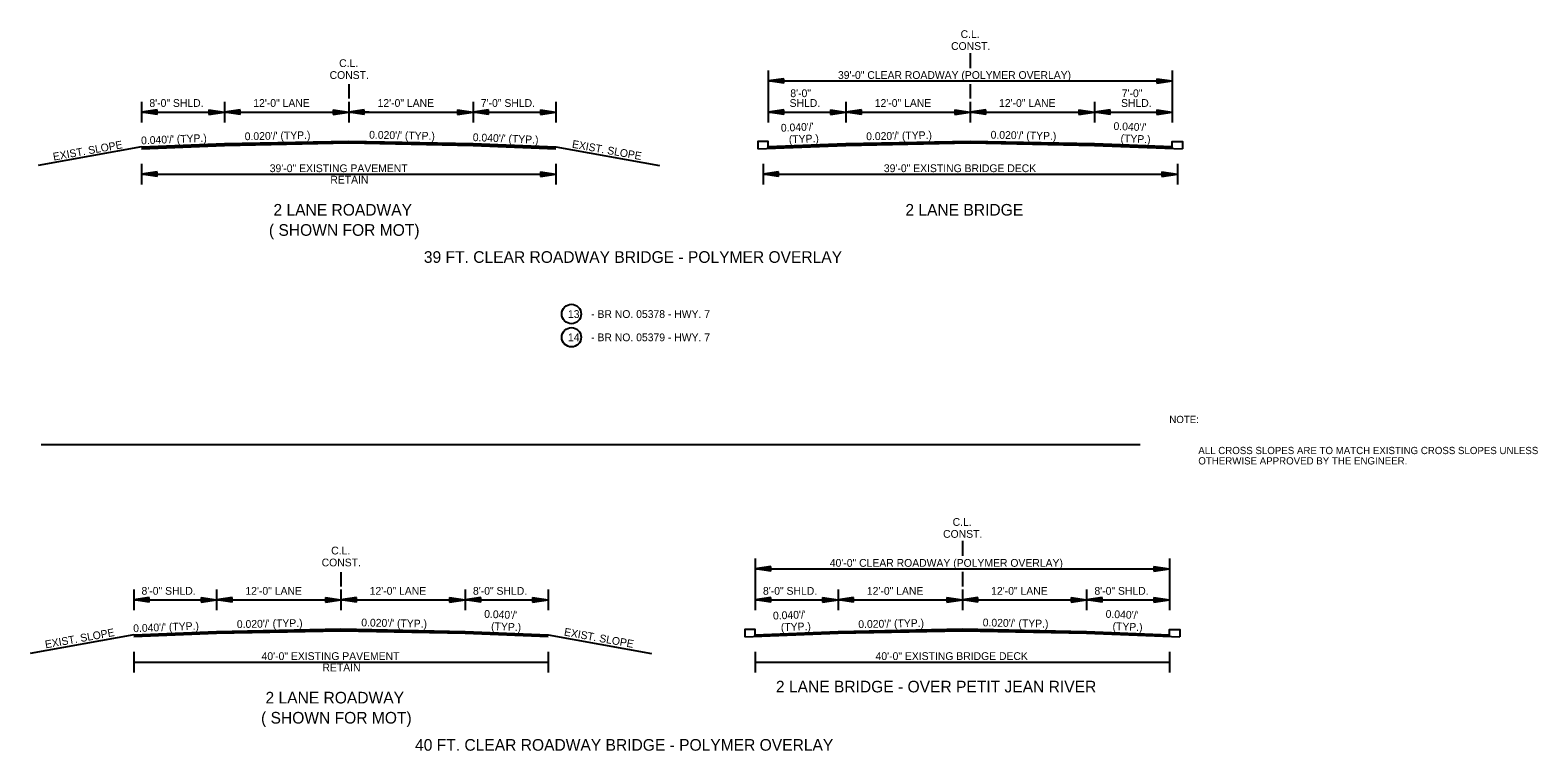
# Model space of a CAD drawing. Extents: x 550980 to 1930787, y -1972975 to 596640.
# Drawn here: x 550998 to 552454, y -1951534 to -1950838 of the extents above; entities that cross this region are included whole.
import ezdxf

# ---------------------------------------------------------------- set-up
doc = ezdxf.new("R2010")
doc.units = 0
for name, color, linetype in [('R_Border', 7, 'Continuous'), ('R_Border Notes', 7, 'Continuous'), ('R_Draft', 7, 'Continuous')]:
    doc.layers.add(name, color=color, linetype=linetype)

# ---------------------------------------------------------------- blocks, each defined once
blk = doc.blocks.new('ARROW')
at = {"layer": 'R_Draft'}
for p, q in [((-2, 0.3), (0, 0)), ((-2, 0.3), (-2, -0.3)), ((-2, 0.25), (-0.334, 0)), ((-2, 0.199), (-0.678, 0)), ((-2, 0.149), (-1.011, 0)), ((-2, 0.097), (-1.35, 0)), ((-2, 0.047), (-1.684, 0)), ((-2, -0.3), (0, 0)), ((-2, -0.098), (-1.35, 0)), ((-2, -0.199), (-0.678, 0)), ((-2, -0.25), (-0.334, 0)), ((-2, -0.149), (-1.011, 0)), ((-2, -0.047), (-1.684, 0))]:
    blk.add_line(p, q, dxfattribs=at)
blk = doc.blocks.new('BPPOLY')
at = {"layer": 'R_Border'}
blk.add_circle((0, 0), 9.34, dxfattribs=at)

msp = doc.modelspace()

# ---------------------------------------------------------------- linework, layer by layer
at = {"layer": 'R_Border'}
for p, q in [((551906.1, -1950859.9), (551906.1, -1950874.4)), ((551711.1, -1950876.9), (551711.1, -1950926.9)), ((552101.1, -1950876.9), (552101.1, -1950926.9)), ((551306.1, -1950889.9), (551306.1, -1950903.9)), ((551711.1, -1950886.9), (552101.1, -1950886.9)), ((551906.1, -1950889.9), (551906.1, -1950903.9)), ((551106.1, -1950906.9), (551106.1, -1950926.9)), ((551186.1, -1950906.9), (551186.1, -1950926.9)), ((551306.1, -1950906.9), (551306.1, -1950926.9)), ((551426.1, -1950906.9), (551426.1, -1950926.9)), ((551506.1, -1950906.9), (551506.1, -1950926.9)), ((551786.1, -1950906.9), (551786.1, -1950926.9)), ((551906.1, -1950906.9), (551906.1, -1950926.9)), ((552026.1, -1950906.9), (552026.1, -1950926.9)), ((551106.1, -1950916.9), (551506.1, -1950916.9)), ((551305.9, -1950916.6), (551325.9, -1950916.6)), ((551711.1, -1950916.9), (552101.1, -1950916.9)), ((551106.1, -1950950.5), (551006.1, -1950968.5)), ((551506.1, -1950950.5), (551606.1, -1950968.5)), ((551106.1, -1950966.9), (551106.1, -1950986.9)), ((551506.1, -1950966.9), (551506.1, -1950986.9)), ((551706.1, -1950966.9), (551706.1, -1950986.9)), ((552106.1, -1950966.9), (552106.1, -1950986.9)), ((551106.1, -1950976.9), (551506.1, -1950976.9)), ((551706.1, -1950976.9), (552106.1, -1950976.9)), ((551009, -1951237.9), (552070.2, -1951237.9)), ((551898.5, -1951331), (551898.5, -1951345.5)), ((551698.5, -1951348), (551698.5, -1951398)), ((551698.5, -1951358), (552098.5, -1951358)), ((551898.5, -1951361), (551898.5, -1951375)), ((552098.5, -1951348), (552098.5, -1951398)), ((551298.5, -1951361.3), (551298.5, -1951375)), ((551098.5, -1951378), (551098.5, -1951398)), ((551098.5, -1951388), (551498.5, -1951388)), ((551178.5, -1951378), (551178.5, -1951398)), ((551298.5, -1951378), (551298.5, -1951398)), ((551418.5, -1951378), (551418.5, -1951398)), ((551498.5, -1951378), (551498.5, -1951398)), ((551698.5, -1951388), (552098.5, -1951388)), ((551778.5, -1951378), (551778.5, -1951398)), ((551898.5, -1951378), (551898.5, -1951398)), ((552018.5, -1951378), (552018.5, -1951398)), ((551098.5, -1951421.6), (550998.5, -1951439.6)), ((551498.5, -1951421.6), (551598.5, -1951439.6)), ((551098.5, -1951438), (551098.5, -1951458)), ((551098.5, -1951448), (551498.5, -1951448)), ((551498.5, -1951438), (551498.5, -1951458)), ((551698.5, -1951438), (551698.5, -1951458)), ((551698.5, -1951448), (552098.5, -1951448)), ((552098.5, -1951438), (552098.5, -1951458))]:
    msp.add_line(p, q, dxfattribs=at)
for points in [[(551106.1, -1950950.5), (551186.1, -1950947.3), (551306.1, -1950944.9), (551426.1, -1950947.3), (551506.1, -1950950.5)], [(551106.1, -1950950.8), (551186.1, -1950947.6), (551306.1, -1950945.2), (551426.1, -1950947.6), (551506.1, -1950950.8)], [(551106.1, -1950951.1), (551186.1, -1950947.9), (551306.1, -1950945.5), (551426.1, -1950947.9), (551506.1, -1950951.1)], [(551106.1, -1950951.4), (551186.1, -1950948.2), (551306.1, -1950945.8), (551426.1, -1950948.2), (551506.1, -1950951.4)], [(551106.1, -1950951.7), (551186.1, -1950948.5), (551306.1, -1950946.1), (551426.1, -1950948.5), (551506.1, -1950951.7)], [(551106.1, -1950952), (551186.1, -1950948.8), (551306.1, -1950946.4), (551426.1, -1950948.8), (551506.1, -1950952)], [(551106.1, -1950952.3), (551186.1, -1950949.1), (551306.1, -1950946.7), (551426.1, -1950949.1), (551506.1, -1950952.3)], [(551711.1, -1950951.8), (551711.1, -1950945.3), (551701.1, -1950945.3), (551701.1, -1950952.5)], [(551701.1, -1950952.5), (551786.1, -1950949.1), (551906.1, -1950946.7), (552026.1, -1950949.1), (552111.1, -1950952.5)], [(551711.1, -1950950.3), (551786.1, -1950947.3), (551906.1, -1950944.9), (552026.1, -1950947.3), (552101.1, -1950950.3)], [(551711.1, -1950950.6), (551786.1, -1950947.6), (551906.1, -1950945.2), (552026.1, -1950947.6), (552101.1, -1950950.6)], [(551711.1, -1950950.9), (551786.1, -1950947.9), (551906.1, -1950945.5), (552026.1, -1950947.9), (552101.1, -1950950.9)], [(551711.1, -1950951.2), (551786.1, -1950948.2), (551906.1, -1950945.8), (552026.1, -1950948.2), (552101.1, -1950951.2)], [(551711.1, -1950951.5), (551786.1, -1950948.5), (551906.1, -1950946.1), (552026.1, -1950948.5), (552101.1, -1950951.5)], [(551711.1, -1950951.8), (551786.1, -1950948.8), (551906.1, -1950946.4), (552026.1, -1950948.8), (552101.1, -1950951.8)], [(552101.1, -1950951.8), (552101.1, -1950945.3), (552111.1, -1950945.3), (552111.1, -1950952.5)], [(551098.5, -1951421.6), (551178.5, -1951418.4), (551298.5, -1951416), (551418.5, -1951418.4), (551498.5, -1951421.6)], [(551098.5, -1951421.9), (551178.5, -1951418.7), (551298.5, -1951416.3), (551418.5, -1951418.7), (551498.5, -1951421.9)], [(551098.5, -1951422.2), (551178.5, -1951419), (551298.5, -1951416.6), (551418.5, -1951419), (551498.5, -1951422.2)], [(551098.5, -1951422.5), (551178.5, -1951419.3), (551298.5, -1951416.9), (551418.5, -1951419.3), (551498.5, -1951422.5)], [(551098.5, -1951422.8), (551178.5, -1951419.6), (551298.5, -1951417.2), (551418.5, -1951419.6), (551498.5, -1951422.8)], [(551098.5, -1951423.1), (551178.5, -1951419.9), (551298.5, -1951417.5), (551418.5, -1951419.9), (551498.5, -1951423.1)], [(551098.5, -1951423.4), (551178.5, -1951420.2), (551298.5, -1951417.8), (551418.5, -1951420.2), (551498.5, -1951423.4)], [(551698.5, -1951423.1), (551698.5, -1951416.6), (551688.5, -1951416.6), (551688.5, -1951423.8)], [(551688.5, -1951423.8), (551778.5, -1951420.2), (551898.5, -1951417.8), (552018.5, -1951420.2), (552108.5, -1951423.8)], [(551698.5, -1951421.6), (551778.5, -1951418.4), (551898.5, -1951416), (552018.5, -1951418.4), (552098.5, -1951421.6)], [(551698.5, -1951421.9), (551778.5, -1951418.7), (551898.5, -1951416.3), (552018.5, -1951418.7), (552098.5, -1951421.9)], [(551698.5, -1951422.2), (551778.5, -1951419), (551898.5, -1951416.6), (552018.5, -1951419), (552098.5, -1951422.2)], [(551698.5, -1951422.5), (551778.5, -1951419.3), (551898.5, -1951416.9), (552018.5, -1951419.3), (552098.5, -1951422.5)], [(551698.5, -1951422.8), (551778.5, -1951419.6), (551898.5, -1951417.2), (552018.5, -1951419.6), (552098.5, -1951422.8)], [(551698.5, -1951423.1), (551778.5, -1951419.9), (551898.5, -1951417.5), (552018.5, -1951419.9), (552098.5, -1951423.1)], [(552098.5, -1951423.8), (552098.5, -1951416.6), (552108.5, -1951416.6), (552108.5, -1951423.8)]]:
    msp.add_lwpolyline(points, dxfattribs=at)

# ---------------------------------------------------------------- block references
at = {"layer": 'R_Border', "xscale": 7.5, "yscale": 7.5, "rotation": 180}
for p in [(551711.1, -1950886.9), (551106.1, -1950916.9), (551186.1, -1950916.9), (551306.1, -1950916.9), (551426.1, -1950916.9), (551711.1, -1950916.9), (551786.1, -1950916.9), (551906.1, -1950916.9), (552026.1, -1950916.9), (551106.1, -1950976.9), (551706.1, -1950976.9), (551698.5, -1951358), (551098.5, -1951388), (551178.5, -1951388), (551298.5, -1951388), (551418.5, -1951388), (551698.5, -1951388), (551778.5, -1951388), (551898.5, -1951388), (552018.5, -1951388)]:
    msp.add_blockref('ARROW', p, dxfattribs=at)
at = {"layer": 'R_Border', "xscale": 7.5, "yscale": 7.5}
for p in [(552101.1, -1950886.9), (551186.1, -1950916.9), (551306.1, -1950916.9), (551426.1, -1950916.9), (551506.1, -1950916.9), (551786.1, -1950916.9), (551906.1, -1950916.9), (552026.1, -1950916.9), (552101.1, -1950916.9), (551506.1, -1950976.9), (552106.1, -1950976.9), (552098.5, -1951358), (551178.5, -1951388), (551298.5, -1951388), (551418.5, -1951388), (551498.5, -1951388), (551778.5, -1951388), (551898.5, -1951388), (552018.5, -1951388), (552098.5, -1951388)]:
    msp.add_blockref('ARROW', p, dxfattribs=at)
at = {"layer": 'R_Border'}
for p in [(551521.1, -1951111.9), (551521.1, -1951134.4)]:
    msp.add_blockref('BPPOLY', p, dxfattribs=at)

# ---------------------------------------------------------------- texts
for s, height, p in [('CONST.', 7.5, (551887.6, -1950856.9)), ('C.L.', 7.5, (551896.8, -1950845.4)), ('C.L.', 7.5, (551296.8, -1950873.4)), ('CONST.', 7.5, (551287.6, -1950884.9)), ('39\'-0" CLEAR ROADWAY (POLYMER OVERLAY)', 7.5, (551778.4, -1950884.9)), ('8\'-0" ', 7.5, (551732.4, -1950902.5)), ('7\'-0" ', 7.5, (552052.4, -1950902.5)), ('8\'-0" SHLD.', 7.5, (551113.6, -1950911.9)), ('12\'-0" LANE', 7.5, (551213.9, -1950911.9)), ('12\'-0" LANE', 7.5, (551333.9, -1950911.9)), ('7\'-0" SHLD.', 7.5, (551433.6, -1950911.9)), ('SHLD.', 7.5, (551731.7, -1950911.9)), ('12\'-0" LANE', 7.5, (551813.9, -1950911.9)), ('12\'-0" LANE', 7.5, (551933.9, -1950911.9)), ('SHLD.', 7.5, (552051.7, -1950911.9)), ('39\'-0" EXISTING PAVEMENT', 7.5, (551229.8, -1950974.9)), ('39\'-0" EXISTING BRIDGE DECK', 7.5, (551822.7, -1950974.9)), ('RETAIN', 7.5, (551288.3, -1950985.9)), ('2 LANE ROADWAY', 11.25, (551233.4, -1951016.9)), ('2 LANE BRIDGE', 11.25, (551843.5, -1951016.9)), ('( SHOWN FOR MOT)', 11.25, (551229, -1951036.4)), ('39 FT. CLEAR ROADWAY BRIDGE - POLYMER OVERLAY', 11.25, (551378.6, -1951062.5)), ('13', 7.5, (551517.7, -1951115.7)), ('- BR NO. 05378 - HWY. 7', 7.5, (551540.1, -1951115.7)), ('14', 7.5, (551517.7, -1951138.2)), ('- BR NO. 05379 - HWY. 7', 7.5, (551540.1, -1951138.2)), ('C.L.', 7.5, (551889.1, -1951316.5)), ('CONST.', 7.5, (551879.9, -1951328)), ('C.L.', 7.5, (551289.1, -1951344.1)), ('CONST.', 7.5, (551279.9, -1951355.6)), ('40\'-0" CLEAR ROADWAY (POLYMER OVERLAY)', 7.5, (551770.5, -1951356)), ('8\'-0" SHLD.', 7.5, (551106, -1951383)), ('12\'-0" LANE', 7.5, (551206.3, -1951383)), ('12\'-0" LANE', 7.5, (551326.3, -1951383)), ('8\'-0" SHLD.', 7.5, (551426, -1951383)), ('8\'-0" SHLD.', 7.5, (551706, -1951383)), ('12\'-0" LANE', 7.5, (551806.3, -1951383)), ('12\'-0" LANE', 7.5, (551926.3, -1951383)), ('8\'-0" SHLD.', 7.5, (552026, -1951383)), ('40\'-0" EXISTING PAVEMENT', 7.5, (551221.9, -1951446)), ('40\'-0" EXISTING BRIDGE DECK', 7.5, (551814.7, -1951446)), ('RETAIN', 7.5, (551280.7, -1951457)), ('2 LANE ROADWAY', 11.25, (551225.7, -1951488)), ('2 LANE BRIDGE - OVER PETIT JEAN RIVER', 11.25, (551718.5, -1951477.3)), ('( SHOWN FOR MOT)', 11.25, (551221.4, -1951507.4)), ('40 FT. CLEAR ROADWAY BRIDGE - POLYMER OVERLAY', 11.25, (551370.1, -1951533.6))]:
    msp.add_text(s, height=height, dxfattribs=at).set_placement(p)
for s, rotation, p in [("0.040'/' (TYP.)", 2.2916, (551105.7, -1950948.1)), ("0.020'/' (TYP.)", 1.1458, (551205.7, -1950944.1)), ("0.020'/' (TYP.)", 358.8542, (551325.7, -1950942.5)), ("0.040'/' (TYP.)", 357.7084, (551425.7, -1950944.9)), ("0.040'/'", 2.2916, (551723.4, -1950935.9)), ('(TYP.)', 2.2916, (551731.1, -1950947.1)), ("0.020'/' (TYP.)", 1.1458, (551805.7, -1950944.1)), ("0.020'/' (TYP.)", 358.8542, (551925.7, -1950942.5)), ("0.040'/'", 357.7084, (552044.3, -1950934.1)), ('(TYP.)', 357.7084, (552051.1, -1950945.9)), ('EXIST. SLOPE', 10.204, (551021.2, -1950963.8)), ('EXIST. SLOPE', 349.796, (551521.2, -1950951.2)), ("0.040'/'", 357.7084, (551436.7, -1951405.2)), ("0.040'/'", 2.2916, (551715.8, -1951407)), ("0.040'/'", 357.7084, (552036.7, -1951405.2)), ('EXIST. SLOPE', 10.204, (551013.5, -1951434.8)), ("0.040'/' (TYP.)", 2.2916, (551098.1, -1951419.2)), ("0.020'/' (TYP.)", 1.1458, (551198.1, -1951415.2)), ("0.020'/' (TYP.)", 358.8542, (551318.1, -1951413.5)), ('(TYP.)', 357.7084, (551443.4, -1951417)), ('EXIST. SLOPE', 349.796, (551513.5, -1951422.3)), ('(TYP.)', 2.2916, (551723.4, -1951418.2)), ("0.020'/' (TYP.)", 1.1458, (551798.1, -1951415.2)), ("0.020'/' (TYP.)", 358.8542, (551918.1, -1951413.5)), ('(TYP.)', 357.7084, (552043.4, -1951417))]:
    msp.add_text(s, height=7.5, rotation=rotation, dxfattribs=at).set_placement(p)
at = {"layer": 'R_Border Notes'}
for s, p in [('NOTE: ', (552098.3, -1951217.2)), ('ALL CROSS SLOPES ARE TO MATCH EXISTING CROSS SLOPES UNLESS ', (552126.3, -1951247.2)), ('OTHERWISE APPROVED BY THE ENGINEER.', (552126.3, -1951257.2))]:
    msp.add_text(s, height=7, dxfattribs=at).set_placement(p)

doc.saveas('drawing.dxf')
